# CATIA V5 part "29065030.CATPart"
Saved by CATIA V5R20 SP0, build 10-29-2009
Part number: 29065030
Definition: NONE
Nomenclature: 29065030
Source: Unknown
Description: 29065030
Bounding box of the stored display mesh (mm): x -15 to 44.548, y -46.5 to 81.048, z -36.5 to 36.5
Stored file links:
  C:\Users\Utente\Desktop\IO LAVORO\3D X SITO CF\X SITO\PLASTICA\RF1\29065030.CATPart
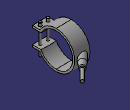
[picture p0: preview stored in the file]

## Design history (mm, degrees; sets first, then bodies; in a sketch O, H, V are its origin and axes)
Body1 "29065030" (main body)
  Solid1: solid without history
